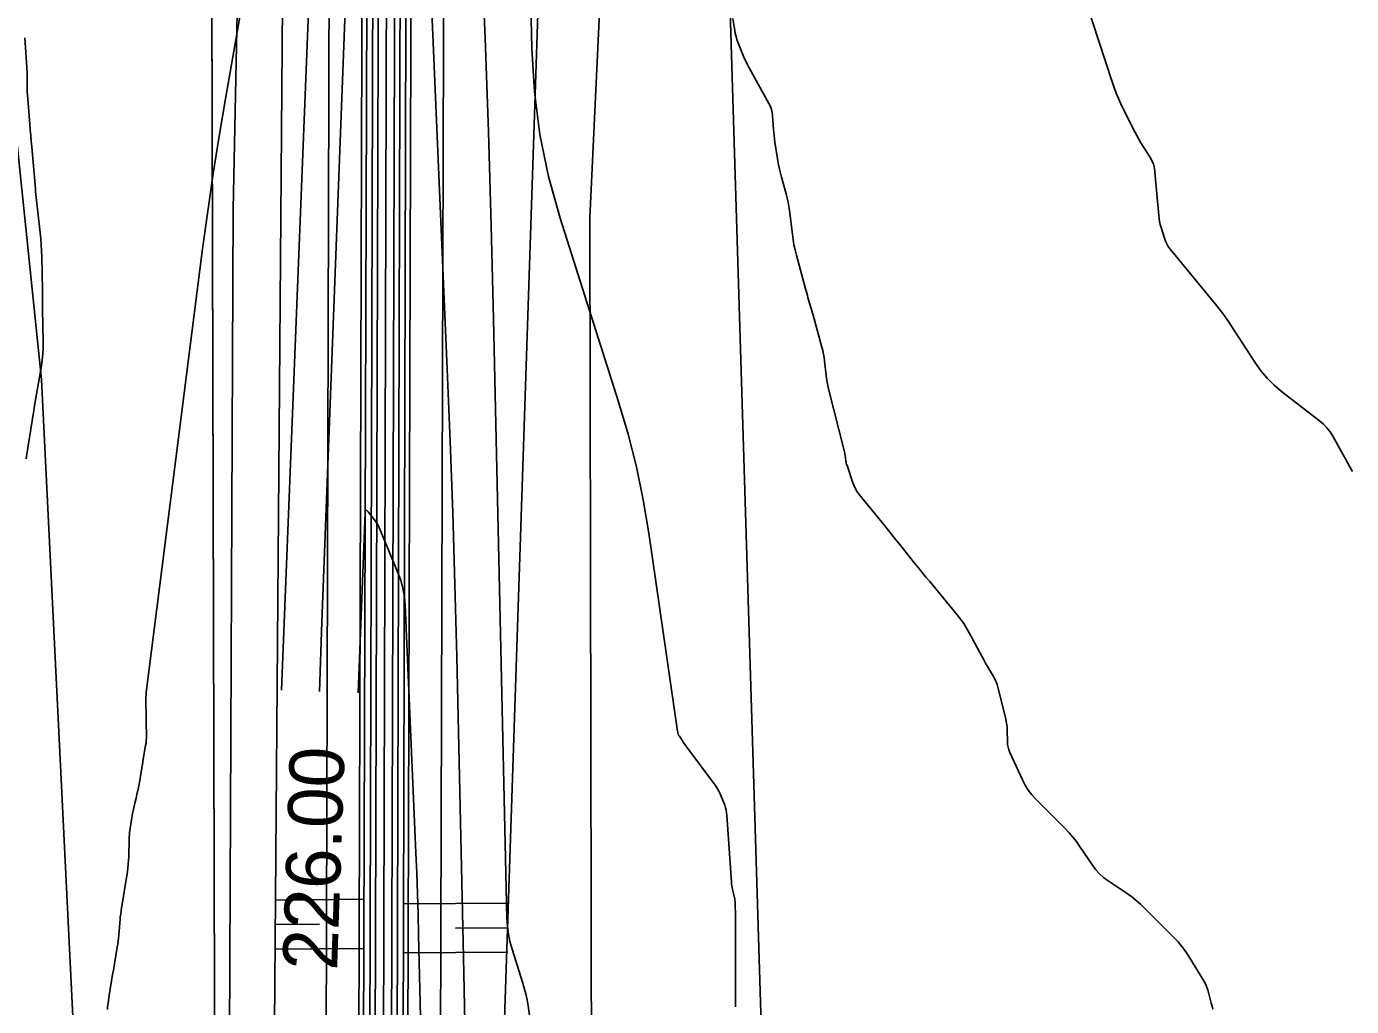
# Model space of a CAD drawing. Extents: x -534410 to -534262, y -1190162 to -1189584.
# Drawn here: x -534372.92 to -534348.65, y -1189778.79 to -1189760.85 of the extents above; entities that cross this region are included whole.
import ezdxf

# ---------------------------------------------------------------- set-up
doc = ezdxf.new("R2010")
doc.units = 0
for name, color, linetype in [('30', 7, 'Continuous'), ('31', 7, 'Continuous'), ('40', 7, 'Continuous'), ('_linie', 7, 'Continuous'), ('_N_osa', 7, 'Continuous'), ('_N_tenká', 7, 'Continuous'), ('_N_tenká_velmi', 7, 'Continuous'), ('_tenka', 7, 'Continuous'), ('_velmi_tenka', 7, 'Continuous'), ('Default', 7, 'Continuous'), ('Hranice parcel', 7, 'Continuous')]:
    doc.layers.add(name, color=color, linetype=linetype)

msp = doc.modelspace()

# ---------------------------------------------------------------- linework, layer by layer
at = {"layer": '30'}
for points in [[(-534367.558, -1189773.027), (-534367.512, -1189771.753), (-534366.662, -1189749.511), (-534366.647, -1189749.405), (-534366.611, -1189749.36), (-534366.556, -1189749.375), (-534366.481, -1189749.452), (-534365.983, -1189750.077), (-534365.978, -1189750.084), (-534365.973, -1189750.092), (-534365.968, -1189750.1), (-534365.964, -1189750.108), (-534365.95, -1189750.142), (-534365.947, -1189750.15), (-534365.945, -1189750.159), (-534365.943, -1189750.168), (-534365.943, -1189750.177), (-534365.213, -1189767.124), (-534365.16, -1189768.439), (-534365.113, -1189769.753), (-534365.074, -1189771.067), (-534365.041, -1189772.382), (-534364.917, -1189777.897), (-534364.89, -1189779.084)], [(-534363.748, -1189757.443), (-534363.663, -1189761.251), (-534363.617, -1189762.041), (-534363.516, -1189762.822), (-534363.358, -1189763.593), (-534363.145, -1189764.355), (-534362.075, -1189767.718), (-534361.899, -1189768.311), (-534361.749, -1189768.91), (-534361.623, -1189769.514), (-534361.522, -1189770.124), (-534360.997, -1189773.751), (-534360.992, -1189773.776), (-534360.984, -1189773.801), (-534360.974, -1189773.824), (-534360.961, -1189773.846), (-534360.903, -1189773.932), (-534360.889, -1189773.954), (-534360.874, -1189773.975), (-534360.859, -1189773.997), (-534360.843, -1189774.018), (-534360.289, -1189774.768), (-534360.262, -1189774.807), (-534360.238, -1189774.848), (-534360.217, -1189774.889), (-534360.199, -1189774.933), (-534360.131, -1189775.109), (-534360.115, -1189775.154), (-534360.103, -1189775.199), (-534360.095, -1189775.245), (-534360.09, -1189775.292), (-534360.007, -1189776.519), (-534360.004, -1189776.552), (-534360, -1189776.585), (-534359.994, -1189776.617), (-534359.987, -1189776.65), (-534359.951, -1189776.798), (-534359.946, -1189776.821), (-534359.942, -1189776.845), (-534359.94, -1189776.869), (-534359.939, -1189776.893), (-534359.936, -1189776.989), (-534359.936, -1189777.013), (-534359.935, -1189777.037), (-534359.935, -1189777.061), (-534359.935, -1189777.085), (-534359.935, -1189778.604), (-534359.935, -1189778.628), (-534359.935, -1189778.652), (-534359.935, -1189778.676), (-534359.934, -1189778.7), (-534359.932, -1189778.799)], [(-534371.442, -1189778.847), (-534371.437, -1189778.793), (-534371.43, -1189778.739), (-534371.423, -1189778.686), (-534371.414, -1189778.632), (-534371.339, -1189778.173), (-534371.338, -1189778.167), (-534371.26, -1189777.71), (-534371.251, -1189777.656), (-534371.244, -1189777.601), (-534371.238, -1189777.546), (-534371.233, -1189777.491), (-534371.21, -1189777.187), (-534371.209, -1189777.174), (-534371.208, -1189777.161), (-534371.206, -1189777.147), (-534371.204, -1189777.134), (-534371.191, -1189777.055), (-534371.187, -1189777.028), (-534371.075, -1189776.323), (-534371.065, -1189776.256), (-534371.058, -1189776.19), (-534371.053, -1189776.123), (-534371.05, -1189776.056), (-534371.041, -1189775.731), (-534371.04, -1189775.692), (-534371.037, -1189775.652), (-534371.034, -1189775.613), (-534371.029, -1189775.574), (-534371.008, -1189775.417), (-534371.002, -1189775.378), (-534370.996, -1189775.339), (-534370.988, -1189775.3), (-534370.98, -1189775.262), (-534370.931, -1189775.044), (-534370.917, -1189774.98), (-534370.902, -1189774.915), (-534370.873, -1189774.786), (-534370.866, -1189774.754), (-534370.859, -1189774.721), (-534370.853, -1189774.689), (-534370.847, -1189774.656), (-534370.798, -1189774.351), (-534370.795, -1189774.334), (-534370.792, -1189774.314), (-534370.79, -1189774.301), (-534370.741, -1189774.013), (-534370.734, -1189773.969), (-534370.73, -1189773.926), (-534370.727, -1189773.882), (-534370.727, -1189773.838), (-534370.732, -1189773.596), (-534370.732, -1189773.573), (-534370.733, -1189773.551), (-534370.733, -1189773.506), (-534370.733, -1189773.484), (-534370.733, -1189773.462), (-534370.738, -1189773.219), (-534370.738, -1189773.175), (-534370.737, -1189773.131), (-534370.734, -1189773.087), (-534370.729, -1189773.043), (-534369.696, -1189764.915), (-534369.604, -1189764.226), (-534369.504, -1189763.539), (-534369.396, -1189762.853), (-534369.28, -1189762.169), (-534368.697, -1189758.85)], [(-534348.626, -1189768.999), (-534348.67, -1189768.922), (-534348.714, -1189768.844), (-534348.757, -1189768.766), (-534348.8, -1189768.689), (-534348.989, -1189768.347), (-534349.038, -1189768.268), (-534349.095, -1189768.194), (-534349.159, -1189768.127), (-534349.23, -1189768.066), (-534349.927, -1189767.528), (-534350.062, -1189767.414), (-534350.187, -1189767.29), (-534350.3, -1189767.156), (-534350.403, -1189767.011), (-534350.799, -1189766.401), (-534350.9, -1189766.251), (-534351.004, -1189766.104), (-534351.113, -1189765.96), (-534351.227, -1189765.819), (-534351.963, -1189764.93), (-534351.996, -1189764.886), (-534352.024, -1189764.839), (-534352.048, -1189764.79), (-534352.067, -1189764.739), (-534352.134, -1189764.527), (-534352.149, -1189764.473), (-534352.161, -1189764.42), (-534352.17, -1189764.365), (-534352.177, -1189764.31), (-534352.246, -1189763.513), (-534352.257, -1189763.438), (-534352.276, -1189763.366), (-534352.304, -1189763.298), (-534352.341, -1189763.232), (-534352.503, -1189762.974), (-534352.542, -1189762.909), (-534352.58, -1189762.843), (-534352.616, -1189762.776), (-534352.651, -1189762.708), (-534352.87, -1189762.261), (-534352.916, -1189762.163), (-534352.958, -1189762.064), (-534352.997, -1189761.963), (-534353.033, -1189761.861), (-534353.994, -1189758.911)]]:
    msp.add_lwpolyline(points, dxfattribs=at)
at = {"layer": '31'}
for points in [[(-534365.123, -1189746.489), (-534365.076, -1189747.773), (-534365.028, -1189749.058), (-534364.976, -1189750.342), (-534364.922, -1189751.626), (-534364.59, -1189759.346), (-534364.52, -1189761.061), (-534364.46, -1189762.776), (-534364.408, -1189764.492), (-534364.365, -1189766.207), (-534364.12, -1189777.185), (-534364.111, -1189777.327), (-534364.093, -1189777.468), (-534364.065, -1189777.607), (-534364.026, -1189777.744), (-534363.833, -1189778.351), (-534363.802, -1189778.458), (-534363.774, -1189778.566), (-534363.752, -1189778.675), (-534363.733, -1189778.785), (-534363.639, -1189779.439)], [(-534368.254, -1189773.003), (-534367.398, -1189751.502), (-534367.341, -1189750.144), (-534367.279, -1189748.788), (-534367.241, -1189748.042)], [(-534359.979, -1189760.702), (-534359.946, -1189760.921), (-534359.936, -1189760.975), (-534359.923, -1189761.029), (-534359.907, -1189761.081), (-534359.888, -1189761.133), (-534359.79, -1189761.378), (-534359.765, -1189761.436), (-534359.74, -1189761.493), (-534359.712, -1189761.548), (-534359.682, -1189761.603), (-534359.319, -1189762.256), (-534359.293, -1189762.31), (-534359.273, -1189762.365), (-534359.259, -1189762.423), (-534359.252, -1189762.482), (-534359.236, -1189762.724), (-534359.231, -1189762.784), (-534359.225, -1189762.844), (-534359.218, -1189762.904), (-534359.209, -1189762.964), (-534359.155, -1189763.304), (-534359.142, -1189763.38), (-534359.126, -1189763.456), (-534359.108, -1189763.532), (-534359.089, -1189763.606), (-534359.003, -1189763.911), (-534358.984, -1189763.987), (-534358.967, -1189764.063), (-534358.953, -1189764.141), (-534358.942, -1189764.218), (-534358.891, -1189764.649), (-534358.878, -1189764.746), (-534358.861, -1189764.843), (-534358.841, -1189764.939), (-534358.817, -1189765.035), (-534358.65, -1189765.648), (-534358.639, -1189765.689), (-534358.628, -1189765.729), (-534358.616, -1189765.77), (-534358.605, -1189765.81), (-534358.558, -1189765.972), (-534358.546, -1189766.013), (-534358.534, -1189766.053), (-534358.523, -1189766.094), (-534358.512, -1189766.135), (-534358.348, -1189766.72), (-534358.332, -1189766.782), (-534358.319, -1189766.845), (-534358.308, -1189766.909), (-534358.299, -1189766.973), (-534358.271, -1189767.23), (-534358.263, -1189767.294), (-534358.253, -1189767.358), (-534358.24, -1189767.421), (-534358.226, -1189767.484), (-534357.942, -1189768.611), (-534357.936, -1189768.634), (-534357.932, -1189768.658), (-534357.927, -1189768.681), (-534357.924, -1189768.704), (-534357.91, -1189768.798), (-534357.907, -1189768.821), (-534357.902, -1189768.844), (-534357.896, -1189768.867), (-534357.889, -1189768.889), (-534357.783, -1189769.202), (-534357.761, -1189769.26), (-534357.733, -1189769.316), (-534357.701, -1189769.369), (-534357.664, -1189769.419), (-534357.198, -1189769.992), (-534357.13, -1189770.077), (-534357.061, -1189770.162), (-534356.992, -1189770.247), (-534356.924, -1189770.333), (-534356.65, -1189770.674), (-534356.582, -1189770.759), (-534356.513, -1189770.844), (-534356.444, -1189770.929), (-534356.374, -1189771.013), (-534355.869, -1189771.622), (-534355.808, -1189771.7), (-534355.751, -1189771.78), (-534355.699, -1189771.863), (-534355.65, -1189771.949), (-534355.421, -1189772.376), (-534355.396, -1189772.424), (-534355.369, -1189772.471), (-534355.343, -1189772.518), (-534355.316, -1189772.565), (-534355.206, -1189772.751), (-534355.181, -1189772.799), (-534355.159, -1189772.847), (-534355.14, -1189772.898), (-534355.125, -1189772.949), (-534354.982, -1189773.529), (-534354.971, -1189773.58), (-534354.963, -1189773.631), (-534354.957, -1189773.683), (-534354.955, -1189773.735), (-534354.95, -1189773.945), (-534354.947, -1189773.996), (-534354.938, -1189774.047), (-534354.924, -1189774.096), (-534354.904, -1189774.145), (-534354.674, -1189774.646), (-534354.625, -1189774.742), (-534354.567, -1189774.833), (-534354.502, -1189774.919), (-534354.429, -1189774.999), (-534353.891, -1189775.537), (-534353.819, -1189775.612), (-534353.751, -1189775.691), (-534353.687, -1189775.773), (-534353.627, -1189775.858), (-534353.394, -1189776.206), (-534353.332, -1189776.289), (-534353.263, -1189776.365), (-534353.187, -1189776.434), (-534353.104, -1189776.495), (-534352.757, -1189776.728), (-534352.672, -1189776.788), (-534352.59, -1189776.852), (-534352.511, -1189776.92), (-534352.436, -1189776.992), (-534351.892, -1189777.536), (-534351.82, -1189777.612), (-534351.753, -1189777.693), (-534351.691, -1189777.777), (-534351.633, -1189777.865), (-534351.363, -1189778.308), (-534351.335, -1189778.358), (-534351.311, -1189778.409), (-534351.291, -1189778.461), (-534351.274, -1189778.515), (-534351.214, -1189778.735), (-534351.2, -1189778.79), (-534351.186, -1189778.845)], [(-534372.933, -1189768.762), (-534372.919, -1189768.68), (-534372.794, -1189767.913), (-534372.791, -1189767.892), (-534372.788, -1189767.871), (-534372.782, -1189767.829), (-534372.779, -1189767.808), (-534372.776, -1189767.787), (-534372.65, -1189767.063), (-534372.634, -1189766.954), (-534372.623, -1189766.844), (-534372.618, -1189766.733), (-534372.617, -1189766.623), (-534372.629, -1189766.014), (-534372.63, -1189765.985), (-534372.63, -1189765.957), (-534372.63, -1189765.929), (-534372.63, -1189765.901), (-534372.631, -1189765.789), (-534372.631, -1189765.761), (-534372.631, -1189765.733), (-534372.632, -1189765.705), (-534372.632, -1189765.676), (-534372.645, -1189765.067), (-534372.648, -1189764.956), (-534372.654, -1189764.845), (-534372.663, -1189764.734), (-534372.674, -1189764.624), (-534372.758, -1189763.868), (-534372.758, -1189763.86), (-534372.758, -1189763.852), (-534372.759, -1189763.833), (-534372.759, -1189763.825), (-534372.759, -1189763.821), (-534372.829, -1189763.052), (-534372.838, -1189762.948), (-534372.847, -1189762.844), (-534372.856, -1189762.741), (-534372.864, -1189762.637), (-534372.906, -1189762.098), (-534372.909, -1189762.056), (-534372.911, -1189762.014), (-534372.912, -1189761.972), (-534372.913, -1189761.929), (-534372.913, -1189761.76), (-534372.913, -1189761.717), (-534372.914, -1189761.675), (-534372.916, -1189761.633), (-534372.918, -1189761.59), (-534372.955, -1189761.052)], [(-534366.847, -1189773.051), (-534366.721, -1189769.754), (-534366.716, -1189769.719), (-534366.705, -1189769.705), (-534366.687, -1189769.71), (-534366.663, -1189769.734), (-534366.553, -1189769.873), (-534366.526, -1189769.908), (-534366.503, -1189769.945), (-534366.482, -1189769.983), (-534366.463, -1189770.023), (-534366.123, -1189770.834), (-534366.067, -1189770.984), (-534366.026, -1189771.137), (-534365.998, -1189771.294), (-534365.984, -1189771.453), (-534365.789, -1189775.978), (-534365.774, -1189776.354), (-534365.761, -1189776.729), (-534365.75, -1189777.105), (-534365.74, -1189777.481), (-534365.707, -1189778.983)]]:
    msp.add_lwpolyline(points, dxfattribs=at)
at = {"layer": '_linie'}
for points in [[(-534366.12, -1189620.81), (-534364.52, -1189627.2), (-534365.69, -1189653.8), (-534366.76, -1189684.81), (-534368.14, -1189748.73), (-534368.38, -1189779.14), (-534368.65, -1189820.64), (-534368.59, -1189847.58), (-534367.2, -1189913.8)], [(-534363.12, -1189621.02), (-534362.79, -1189621.58), (-534361.82, -1189627.79), (-534363.46, -1189653.55), (-534365.47, -1189684.77), (-534366.65, -1189748.83), (-534366.75, -1189779.47), (-534366.9, -1189820.47), (-534366.95, -1189846.72), (-534366.338, -1189888.804), (-534363.85, -1189911.95), (-534357.07, -1189929.19), (-534352.334, -1189940.856)], [(-534359.03, -1189621.26), (-534359.41, -1189621.83), (-534360.84, -1189627.76), (-534362.92, -1189653.56), (-534364.64, -1189685), (-534365.94, -1189748.9), (-534366.02, -1189779.52), (-534366.03, -1189820.5), (-534366.48, -1189846.73), (-534365.511, -1189888.873), (-534362.72, -1189912.12), (-534356.62, -1189928.64), (-534351.589, -1189940.594)]]:
    msp.add_lwpolyline(points, dxfattribs=at)
at = {"layer": '_N_osa'}
msp.add_lwpolyline([(-534351.95, -1189940.722), (-534356.845, -1189928.915), (-534363.285, -1189912.035), (-534365.925, -1189888.838), (-534366.715, -1189846.725), (-534366.465, -1189820.485), (-534366.385, -1189779.495), (-534366.295, -1189748.865), (-534365.055, -1189684.885), (-534363.19, -1189653.555), (-534361.333, -1189627.822)], dxfattribs=at)
at = {"layer": '_N_tenká'}
for points in [[(-534352.92, -1189941.124), (-534357.821, -1189929.303), (-534364.313, -1189912.285), (-534366.973, -1189888.908), (-534367.765, -1189846.73), (-534367.515, -1189820.479), (-534367.435, -1189779.492), (-534367.345, -1189748.853), (-534366.104, -1189684.844), (-534364.238, -1189653.486), (-534362.424, -1189628.352), (-534361.782, -1189627.792)], [(-534352.089, -1189940.779), (-534356.984, -1189928.97), (-534363.432, -1189912.071), (-534366.074, -1189888.848), (-534366.865, -1189846.726), (-534366.615, -1189820.484), (-534366.535, -1189779.495), (-534366.445, -1189748.863), (-534365.205, -1189684.879), (-534363.34, -1189653.545), (-534361.483, -1189627.812)], [(-534351.812, -1189940.664), (-534356.706, -1189928.86), (-534363.138, -1189911.999), (-534365.775, -1189888.828), (-534366.565, -1189846.724), (-534366.315, -1189820.486), (-534366.235, -1189779.495), (-534366.145, -1189748.867), (-534364.905, -1189684.891), (-534363.04, -1189653.565), (-534361.184, -1189627.831)], [(-534350.98, -1189940.319), (-534355.869, -1189928.527), (-534362.257, -1189911.785), (-534364.876, -1189888.769), (-534365.665, -1189846.72), (-534365.415, -1189820.491), (-534365.335, -1189779.498), (-534365.245, -1189748.877), (-534364.006, -1189684.926), (-534362.142, -1189653.624), (-534360.329, -1189628.488), (-534360.884, -1189627.851)]]:
    msp.add_lwpolyline(points, dxfattribs=at)
at = {"layer": '_N_tenká_velmi'}
for points in [[(-534352.366, -1189940.894), (-534357.263, -1189929.081), (-534363.726, -1189912.142), (-534366.374, -1189888.868), (-534367.165, -1189846.727), (-534366.915, -1189820.482), (-534366.835, -1189779.494), (-534366.745, -1189748.86), (-534365.505, -1189684.867), (-534363.639, -1189653.525), (-534361.782, -1189627.792)], [(-534352.181, -1189940.817), (-534357.077, -1189929.007), (-534363.53, -1189912.095), (-534366.174, -1189888.855), (-534366.965, -1189846.726), (-534366.715, -1189820.484), (-534366.635, -1189779.494), (-534366.545, -1189748.862), (-534365.305, -1189684.875), (-534363.439, -1189653.539), (-534361.583, -1189627.805)], [(-534351.719, -1189940.626), (-534356.613, -1189928.823), (-534363.04, -1189911.975), (-534365.675, -1189888.822), (-534366.465, -1189846.724), (-534366.215, -1189820.486), (-534366.135, -1189779.496), (-534366.045, -1189748.868), (-534364.805, -1189684.895), (-534362.941, -1189653.571), (-534361.084, -1189627.838)], [(-534351.534, -1189940.549), (-534356.427, -1189928.749), (-534362.844, -1189911.928), (-534365.475, -1189888.808), (-534366.265, -1189846.723), (-534366.015, -1189820.488), (-534365.935, -1189779.496), (-534365.845, -1189748.87), (-534364.605, -1189684.903), (-534362.741, -1189653.585), (-534360.884, -1189627.851)]]:
    msp.add_lwpolyline(points, dxfattribs=at)
at = {"layer": '_tenka'}
for points in [[(-534349.13, -1189939.73), (-534354.63, -1189926.96), (-534362.03, -1189907.65), (-534364.521, -1189888.74), (-534364.47, -1189846.64), (-534364.29, -1189820.63), (-534364.22, -1189780.69), (-534363.18, -1189749.38), (-534362.5, -1189685.39), (-534360.27, -1189651.6), (-534357.03, -1189627.34), (-534354.77, -1189620.37)], [(-534366.12, -1189620.81), (-534364.52, -1189627.2), (-534365.69, -1189653.8), (-534366.76, -1189684.81), (-534368.14, -1189748.73), (-534368.38, -1189779.14), (-534368.65, -1189820.64), (-534368.59, -1189847.58), (-534367.2, -1189913.8)], [(-534366.12, -1189620.81), (-534364.52, -1189627.2), (-534365.69, -1189653.8), (-534366.76, -1189684.81), (-534368.14, -1189748.73), (-534368.38, -1189779.14), (-534368.65, -1189820.64), (-534368.59, -1189847.58), (-534367.2, -1189913.8)], [(-534363.12, -1189621.02), (-534362.79, -1189621.58), (-534361.82, -1189627.79), (-534363.46, -1189653.55), (-534365.47, -1189684.77), (-534366.65, -1189748.83), (-534366.75, -1189779.47), (-534366.9, -1189820.47), (-534366.95, -1189846.72), (-534366.338, -1189888.804), (-534363.85, -1189911.95), (-534357.07, -1189929.19), (-534352.334, -1189940.856)], [(-534363.12, -1189621.02), (-534362.79, -1189621.58), (-534361.82, -1189627.79), (-534363.46, -1189653.55), (-534365.47, -1189684.77), (-534366.65, -1189748.83), (-534366.75, -1189779.47), (-534366.9, -1189820.47), (-534366.95, -1189846.72), (-534366.338, -1189888.804), (-534363.85, -1189911.95), (-534357.07, -1189929.19), (-534352.334, -1189940.856)], [(-534359.03, -1189621.26), (-534359.41, -1189621.83), (-534360.84, -1189627.76), (-534362.92, -1189653.56), (-534364.64, -1189685), (-534365.94, -1189748.9), (-534366.02, -1189779.52), (-534366.03, -1189820.5), (-534366.48, -1189846.73), (-534365.511, -1189888.873), (-534362.72, -1189912.12), (-534356.62, -1189928.64), (-534351.589, -1189940.594)], [(-534359.03, -1189621.26), (-534359.41, -1189621.83), (-534360.84, -1189627.76), (-534362.92, -1189653.56), (-534364.64, -1189685), (-534365.94, -1189748.9), (-534366.02, -1189779.52), (-534366.03, -1189820.5), (-534366.48, -1189846.73), (-534365.511, -1189888.873), (-534362.72, -1189912.12), (-534356.62, -1189928.64), (-534351.589, -1189940.594)], [(-534368.65, -1189626.81), (-534368.65, -1189626.81), (-534367.31, -1189654.04), (-534367.67, -1189685.23), (-534369.56, -1189748.93), (-534369.48, -1189778.6), (-534369.45, -1189820.62), (-534369.45, -1189847.87), (-534371.206, -1189896.071), (-534372.39, -1189914.47)]]:
    msp.add_lwpolyline(points, dxfattribs=at)
at = {"layer": '_velmi_tenka'}
for p, q in [((-534368.369, -1189776.846), (-534366.747, -1189776.831)), ((-534364.112, -1189776.902), (-534366.017, -1189776.914)), ((-534368.365, -1189777.296), (-534367.554, -1189777.288)), ((-534364.109, -1189777.352), (-534365.062, -1189777.358)), ((-534368.361, -1189777.746), (-534366.739, -1189777.731)), ((-534364.106, -1189777.802), (-534366.012, -1189777.814))]:
    msp.add_line(p, q, dxfattribs=at)
at = {"layer": 'Default'}
for p, q in [((-534369.56, -1189748.93), (-534369.48, -1189778.6)), ((-534369.48, -1189778.6), (-534369.45, -1189820.62))]:
    msp.add_line(p, q, dxfattribs=at)
msp.add_lwpolyline([(-534349.13, -1189939.73), (-534354.63, -1189926.96), (-534362.03, -1189907.65), (-534364.521, -1189888.74), (-534364.47, -1189846.64), (-534364.29, -1189820.63), (-534364.22, -1189780.69), (-534363.18, -1189749.38), (-534362.5, -1189685.39), (-534360.27, -1189651.6), (-534357.03, -1189627.34), (-534354.77, -1189620.37)], dxfattribs=at)
at = {"layer": 'Hranice parcel'}
for p, q in [((-534369.14, -1189764.19), (-534367.77, -1189697.34)), ((-534369.38, -1189820.8), (-534369.14, -1189764.19))]:
    msp.add_line(p, q, dxfattribs=at)
for points in [[(-534359.48, -1189697.97), (-534362.6, -1189764.35), (-534362.34, -1189901.56)], [(-534359.48, -1189697.97), (-534360.42, -1189747.8), (-534359.17, -1189788.69), (-534356.86, -1189843.2), (-534358.53, -1189915.98)], [(-534369.38, -1189820.8), (-534370.35, -1189813.98), (-534372.65, -1189767.31), (-534373.49, -1189759.21)]]:
    msp.add_lwpolyline(points, dxfattribs=at)

# ---------------------------------------------------------------- texts
at = {"layer": '40'}
msp.add_text('226.00', height=1, rotation=88.0426, dxfattribs=at).set_placement((-534367.233, -1189778.143))

doc.saveas('drawing.dxf')
